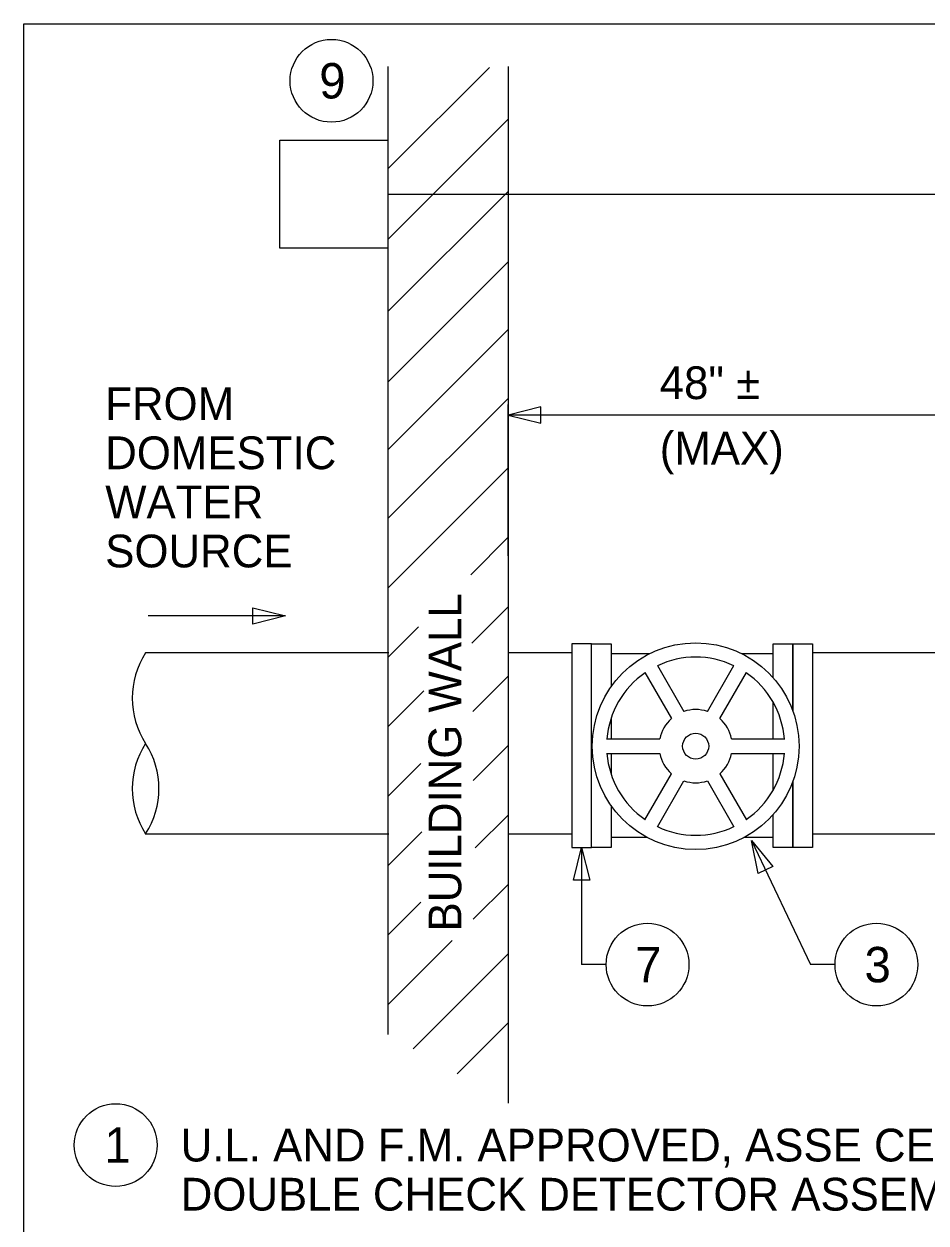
# Model space of a CAD drawing. Extents: x 10462 to 10511.2, y 10121.5 to 10170.9.
# Drawn here: x 10462.02 to 10480.39, y 10146.47 to 10170.89 of the extents above; entities that cross this region are included whole.
import ezdxf

# ---------------------------------------------------------------- set-up
doc = ezdxf.new("R2010")
doc.units = 0
for name, color, linetype in [('G-ANNO-NPLT', 7, 'Continuous'), ('G-ANNO-SYMB', 7, 'Continuous'), ('G-DETL-LINE', 7, 'Continuous'), ('G-DETL-TEXT', 7, 'Continuous')]:
    doc.layers.add(name, color=color, linetype=linetype)

msp = doc.modelspace()

# ---------------------------------------------------------------- linework, layer by layer
at = {"layer": 'G-ANNO-NPLT'}
msp.add_lwpolyline([(10462.021, 10170.89), (10511.163, 10170.89), (10511.163, 10125.39), (10462.021, 10125.39)], close=True, dxfattribs=at)
at = {"layer": 'G-ANNO-SYMB'}
for centre in [(10468.283, 10169.733), (10474.719, 10151.735), (10479.38, 10151.735), (10463.888, 10148.059)]:
    msp.add_circle(centre, 0.843, dxfattribs=at)
at = {"layer": 'G-DETL-LINE'}
for p, q in [((10469.431, 10170.026), (10469.431, 10150.313)), ((10469.431, 10167.938), (10471.5, 10170.007)), ((10471.879, 10170.026), (10471.879, 10148.912)), ((10469.431, 10166.5), (10471.879, 10168.949)), ((10469.431, 10165.033), (10471.879, 10167.481)), ((10469.431, 10167.426), (10489.303, 10167.426)), ((10469.431, 10163.598), (10471.879, 10166.046)), ((10469.431, 10162.219), (10471.879, 10164.667)), ((10469.431, 10160.818), (10471.879, 10163.266)), ((10469.431, 10159.404), (10471.879, 10161.852)), ((10471.117, 10159.675), (10471.879, 10160.438)), ((10471.138, 10158.282), (10471.879, 10159.023)), ((10469.431, 10157.989), (10470.054, 10158.613)), ((10469.45, 10158.081), (10464.498, 10158.081)), ((10473.176, 10158.081), (10471.879, 10158.081)), ((10474.752, 10158.063), (10473.977, 10158.063)), ((10477.276, 10158.063), (10476.645, 10158.063)), ((10481.224, 10158.081), (10478.077, 10158.081)), ((10474.919, 10157.827), (10475.46, 10156.89)), ((10475.938, 10156.89), (10476.479, 10157.827)), ((10471.159, 10156.889), (10471.879, 10157.609)), ((10474.665, 10157.681), (10475.206, 10156.744)), ((10476.192, 10156.744), (10476.733, 10157.681)), ((10469.431, 10156.575), (10470.165, 10157.309)), ((10473.885, 10156.332), (10474.968, 10156.332)), ((10476.43, 10156.332), (10477.513, 10156.332)), ((10471.169, 10155.485), (10471.879, 10156.195)), ((10469.431, 10155.161), (10470.1, 10155.83)), ((10473.885, 10156.034), (10474.968, 10156.034)), ((10476.43, 10156.034), (10477.513, 10156.034)), ((10474.665, 10154.685), (10475.206, 10155.623)), ((10476.192, 10155.623), (10476.733, 10154.685)), ((10474.919, 10154.539), (10475.46, 10155.476)), ((10475.938, 10155.476), (10476.479, 10154.539)), ((10471.211, 10154.112), (10471.879, 10154.781)), ((10469.45, 10154.388), (10464.491, 10154.388)), ((10469.431, 10153.747), (10470.125, 10154.441)), ((10473.176, 10154.388), (10471.879, 10154.388)), ((10482.211, 10154.388), (10478.077, 10154.388)), ((10473.377, 10154.12), (10473.377, 10151.735)), ((10474.715, 10154.323), (10473.977, 10154.323)), ((10477.276, 10154.323), (10476.683, 10154.323)), ((10476.837, 10154.265), (10478.037, 10151.735)), ((10471.171, 10152.659), (10471.879, 10153.367)), ((10469.431, 10152.333), (10470.101, 10153.003)), ((10469.431, 10150.918), (10470.737, 10152.225)), ((10469.945, 10150.019), (10471.879, 10151.952)), ((10473.877, 10151.735), (10473.377, 10151.735)), ((10478.537, 10151.735), (10478.037, 10151.735)), ((10470.839, 10149.508), (10471.879, 10150.548))]:
    msp.add_line(p, q, dxfattribs=at)
for points in [[(10467.228, 10168.527), (10469.431, 10168.527), (10469.431, 10166.325), (10467.228, 10166.325)], [(10473.21, 10153.454), (10473.377, 10154.12), (10473.543, 10153.454)], [(10476.972, 10153.591), (10476.837, 10154.265), (10477.273, 10153.734)]]:
    msp.add_lwpolyline(points, close=True, dxfattribs=at)
for points in [[(10473.577, 10156.904), (10473.577, 10158.265), (10473.176, 10158.265), (10473.176, 10154.12), (10473.577, 10154.12), (10473.577, 10155.462)], [(10473.977, 10154.972), (10473.977, 10154.12), (10473.577, 10154.12), (10473.577, 10158.265), (10473.977, 10158.265), (10473.977, 10157.394)], [(10477.276, 10157.577), (10477.276, 10158.265), (10477.676, 10158.265), (10477.676, 10156.904)], [(10477.676, 10156.904), (10477.676, 10158.265), (10478.077, 10158.265), (10478.077, 10154.12), (10477.676, 10154.12), (10477.676, 10155.462)], [(10477.276, 10156.332), (10477.276, 10157.08)], [(10473.977, 10156.755), (10473.977, 10156.332)], [(10473.977, 10156.034), (10473.977, 10155.611)], [(10477.276, 10155.286), (10477.276, 10156.034)], [(10477.676, 10155.462), (10477.676, 10154.12), (10477.276, 10154.12), (10477.276, 10154.789)]]:
    msp.add_lwpolyline(points, dxfattribs=at)
for radius in [2.105, 0.265]:
    msp.add_circle((10475.699, 10156.183), radius, dxfattribs=at)
for centre, radius, start, end in [((10465.916, 10157.16), 1.691, 147.0136, 212.9864), ((10475.699, 10156.183), 1.814, 64.6295, 115.3705), ((10475.699, 10156.183), 1.814, 124.6295, 175.2858), ((10475.699, 10156.183), 1.814, 4.7142, 55.3705), ((10475.699, 10156.183), 0.746, 71.3127, 108.6873), ((10475.699, 10156.183), 0.746, 131.3127, 168.4779), ((10475.699, 10156.183), 0.746, 11.5221, 48.6873), ((10465.916, 10155.318), 1.691, 147.0136, 212.9864), ((10463.079, 10155.318), 1.691, 327.0136, 32.9864), ((10475.699, 10156.183), 1.814, 184.7142, 235.3705), ((10475.699, 10156.183), 0.746, 191.5221, 228.6873), ((10475.699, 10156.183), 0.746, 311.3127, 348.4779), ((10475.699, 10156.183), 1.814, 304.6295, 355.2858), ((10475.699, 10156.183), 0.746, 251.3127, 288.6873), ((10475.699, 10156.183), 1.814, 244.6295, 295.3705)]:
    msp.add_arc(centre, radius, start, end, dxfattribs=at)
at = {"layer": 'G-DETL-TEXT'}
for p, q in [((10471.879, 10160.06), (10471.879, 10163.138)), ((10473.577, 10162.926), (10471.879, 10162.926)), ((10471.879, 10162.926), (10471.879, 10162.926)), ((10481.224, 10162.926), (10473.577, 10162.926)), ((10467.345, 10158.836), (10464.547, 10158.836))]:
    msp.add_line(p, q, dxfattribs=at)
for points in [[(10472.546, 10163.093), (10471.879, 10162.926), (10472.546, 10162.76)], [(10466.678, 10159.002), (10467.345, 10158.836), (10466.678, 10158.669)]]:
    msp.add_lwpolyline(points, close=True, dxfattribs=at)

# ---------------------------------------------------------------- texts
at = {"layer": 'G-ANNO-SYMB'}
for s, p in [('9', (10468.033, 10169.373)), ('7', (10474.467, 10151.374)), ('3', (10479.137, 10151.374)), ('1', (10463.658, 10147.699))]:
    msp.add_text(s, height=0.721, dxfattribs=at).set_placement(p)
at = {"layer": 'G-DETL-TEXT'}
for s, height, p in [('48" ±', 0.6667, (10474.967, 10163.251)), ('FROM', 0.6667, (10463.675, 10162.824)), ('DOMESTIC', 0.6667, (10463.675, 10161.824)), ('(MAX)', 0.6667, (10474.967, 10161.918)), ('WATER', 0.6667, (10463.675, 10160.824)), ('SOURCE', 0.6667, (10463.675, 10159.824)), ('U.L. AND F.M. APPROVED, ASSE CERTIFIED,', 0.66667, (10465.212, 10147.726)), ('DOUBLE CHECK DETECTOR ASSEMBLY.', 0.66667, (10465.212, 10146.726))]:
    msp.add_text(s, height=height, dxfattribs=at).set_placement(p)
msp.add_text('BUILDING WALL', height=0.66667, rotation=90, dxfattribs=at).set_placement((10470.927, 10152.41))

doc.saveas('drawing.dxf')
